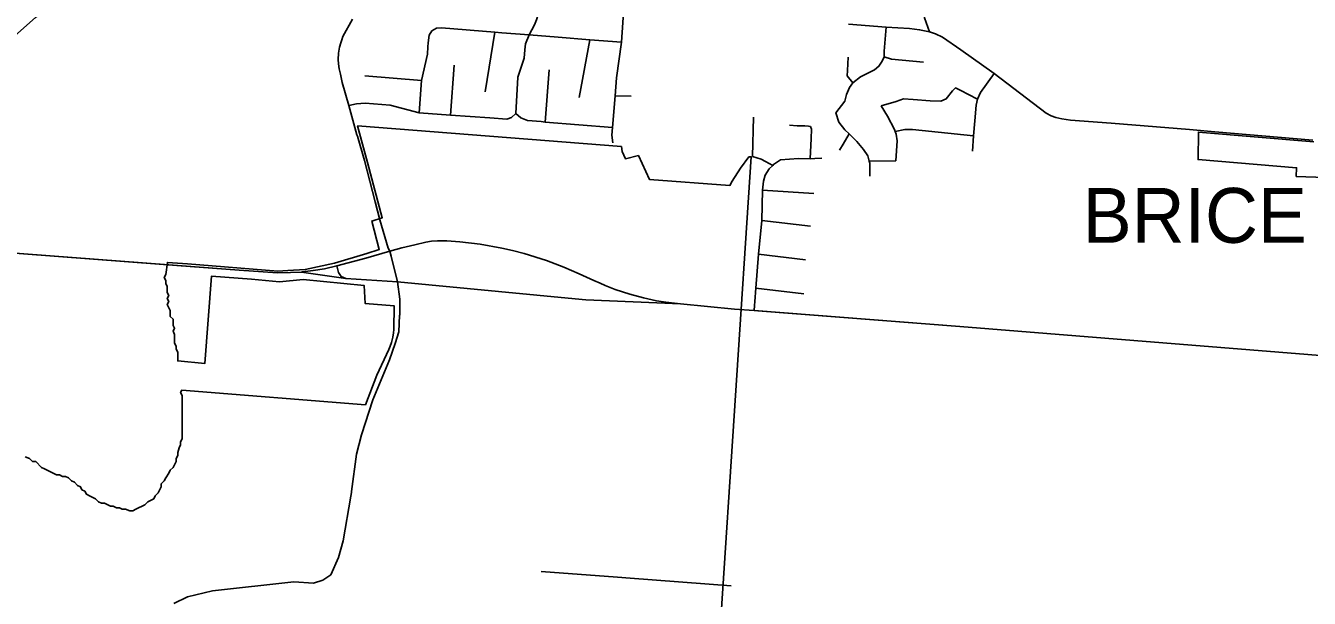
# Model space of a CAD drawing. Extents: x 1729596 to 1934326, y 644115 to 911751.
# Drawn here: x 1863218 to 1874925, y 694653 to 699875 of the extents above; entities that cross this region are included whole.
import ezdxf

# ---------------------------------------------------------------- set-up
doc = ezdxf.new("R2010")
doc.units = 0
for name, color, linetype in [('GM_X_City_Street', 7, 'Continuous'), ('GM_X_Corporation', 7, 'Continuous'), ('GM_X_Corporation_Text', 7, 'Continuous'), ('GM_X_County_Road', 7, 'Continuous'), ('GM_X_Interstate_Route', 7, 'Continuous'), ('GM_X_Township', 7, 'Continuous'), ('GM_X_Township_Road', 7, 'Continuous')]:
    doc.layers.add(name, color=color, linetype=linetype)

msp = doc.modelspace()

# ---------------------------------------------------------------- linework, layer by layer
at = {"layer": 'GM_X_City_Street'}
for points in [[(1867689, 699074), (1867705, 699405), (1867764, 699580), (1867769, 699656), (1867777, 699710), (1867811, 699792), (1867859, 699882), (1867878, 699928), (1867890, 699967), (1867902, 700098), (1867921, 700440), (1867930, 700572), (1867936, 700755), (1867950, 700831), (1867977, 700904), (1867994, 700938), (1868035, 701005)], [(1871460, 699819), (1871415, 699946), (1871415, 700030), (1871420, 700173), (1871424, 700234)], [(1868572, 698806), (1868565, 698876), (1868570, 698945), (1868593, 699236), (1868606, 699398), (1868653, 699725), (1868674, 700037)], [(1866244, 698866), (1866239, 698881), (1866165, 699146), (1866104, 699357), (1866088, 699432), (1866078, 699480), (1866071, 699526), (1866067, 699566), (1866070, 699624), (1866080, 699680), (1866091, 699717), (1866100, 699747), (1866111, 699776), (1866198, 699935)], [(1866922, 699827), (1866964, 699853), (1867010, 699856), (1867496, 699815), (1867561, 699811), (1867811, 699792), (1868074, 699771), (1868363, 699747), (1868653, 699725)], [(1870917, 698502), (1870917, 698622), (1870912, 698639), (1870897, 698688), (1870860, 698747), (1870799, 698819), (1870727, 698889), (1870690, 698925), (1870633, 698996), (1870607, 699079), (1870690, 699188), (1870705, 699246), (1870731, 699310), (1870762, 699355), (1870830, 699409), (1870960, 699473), (1871000, 699505), (1871028, 699550), (1871046, 699590), (1871048, 699643), (1871065, 699862)], [(1870722, 699888), (1871065, 699862), (1871277, 699848), (1871371, 699838), (1871460, 699819), (1871514, 699800), (1871580, 699770), (1871747, 699655), (1872052, 699438), (1872525, 699078), (1872570, 699053), (1872613, 699038), (1872668, 699024), (1872748, 699013), (1873117, 698986), (1873833, 698927), (1874063, 698907)], [(1866807, 699079), (1866829, 699375), (1866881, 699616), (1866885, 699683), (1866888, 699719), (1866899, 699787), (1866922, 699827)], [(1867407, 699273), (1867496, 699815)], [(1868267, 699221), (1868363, 699747)], [(1867092, 699059), (1867127, 699515)], [(1870762, 699355), (1870711, 699419), (1870712, 699467), (1870719, 699588)], [(1871046, 699590), (1871114, 699571), (1871407, 699543)], [(1866312, 699417), (1866829, 699375)], [(1867957, 698996), (1867992, 699471)], [(1871853, 698732), (1871863, 698871), (1871873, 699006), (1871885, 699149), (1871899, 699206), (1871927, 699266), (1872052, 699438)], [(1871020, 699143), (1871158, 699184), (1871223, 699208), (1871311, 699203), (1871468, 699190), (1871564, 699185), (1871614, 699209), (1871672, 699281), (1871699, 699307), (1871745, 699283), (1871815, 699246), (1871899, 699206)], [(1866165, 699146), (1866236, 699163), (1866313, 699167), (1866542, 699151), (1866807, 699079), (1867092, 699059), (1867450, 699033), (1867606, 699022), (1867650, 699039), (1867689, 699074)], [(1868593, 699236), (1868740, 699231)], [(1867689, 699074), (1867734, 699033), (1867793, 699010), (1867919, 699000), (1867957, 698996), (1868570, 698945)], [(1869845, 698682), (1869856, 699040)], [(1871153, 698643), (1871165, 698825), (1871156, 698886), (1871148, 698910), (1871141, 698928), (1871078, 699051), (1871020, 699143)], [(1870371, 698662), (1870381, 698847), (1870385, 698931), (1870375, 698954), (1870357, 698960), (1870325, 698961), (1870253, 698962), (1870184, 698967)], [(1871148, 698910), (1871237, 698928), (1871307, 698927), (1871863, 698871)], [(1866550, 697772), (1866538, 697818), (1866524, 697845), (1866448, 698105), (1866404, 698269), (1866307, 698645), (1866244, 698866)], [(1870639, 698739), (1870674, 698795), (1870727, 698889)], [(1874063, 698907), (1874957, 698831)], [(1869845, 698682), (1869926, 698658), (1869965, 698637), (1870031, 698601)], [(1869861, 697276), (1869864, 697323), (1869867, 697360), (1869878, 697481), (1869902, 697791), (1869931, 698097), (1869938, 698375), (1869948, 698457), (1869963, 698511), (1869998, 698568), (1870031, 698601)], [(1870031, 698601), (1870037, 698610), (1870102, 698650), (1870267, 698663), (1870371, 698662), (1870414, 698663), (1870480, 698666)], [(1870912, 698639), (1871153, 698643)], [(1869938, 698375), (1870407, 698346)], [(1869931, 698097), (1870375, 698046)], [(1862259, 697869), (1862555, 697842), (1864476, 697696)], [(1869902, 697791), (1870329, 697740)], [(1869878, 697481), (1870316, 697430)], [(1869895, 697274), (1871736, 697131), (1875175, 696856)]]:
    msp.add_lwpolyline(points, dxfattribs=at)
at = {"layer": 'GM_X_Corporation'}
for points in [[(1869550, 694325), (1869833, 698679), (1869814, 698680), (1869737, 698577), (1869660, 698456), (1869641, 698418), (1868907, 698473), (1868806, 698690), (1868687, 698662), (1868657, 698726), (1868651, 698772), (1866245, 698962), (1866336, 698628), (1866470, 698123), (1866374, 698093), (1866443, 697834), (1866328, 697798), (1866034, 697709), (1865767, 697650), (1865608, 697641), (1865518, 697637), (1864693, 697702), (1864510, 697716), (1864495, 697606), (1864481, 697579), (1864495, 697551), (1864495, 697524), (1864508, 697497), (1864508, 697469), (1864508, 697442), (1864522, 697415), (1864508, 697388), (1864522, 697360), (1864508, 697333), (1864536, 697279), (1864536, 697224), (1864563, 697197), (1864563, 697142), (1864576, 697115), (1864563, 697088), (1864576, 697060), (1864576, 696979), (1864590, 696951), (1864590, 696924), (1864604, 696897), (1864604, 696818), (1864851, 696794), (1864914, 697591), (1865278, 697562), (1865532, 697538), (1865750, 697559), (1866305, 697505), (1866315, 697341), (1866579, 697320), (1866574, 697105), (1866572, 697073), (1866566, 697034), (1866555, 696987), (1866543, 696952), (1866530, 696922), (1866419, 696689), (1866317, 696418), (1864641, 696550), (1864631, 696529), (1864645, 696501), (1864645, 696229), (1864645, 696106), (1864631, 696079), (1864631, 696052), (1864617, 696024), (1864604, 695983), (1864604, 695956), (1864590, 695929), (1864590, 695902), (1864563, 695847), (1864536, 695820), (1864522, 695793), (1864495, 695752), (1864481, 695724), (1864454, 695697), (1864454, 695670), (1864426, 695615), (1864399, 695588), (1864386, 695561), (1864331, 695533), (1864304, 695506), (1864222, 695465), (1864195, 695452), (1864167, 695452), (1864127, 695465), (1864099, 695465), (1864072, 695479), (1864045, 695479), (1864017, 695493), (1863990, 695493), (1863936, 695520), (1863908, 695520), (1863881, 695533), (1863854, 695561), (1863799, 695588), (1863772, 695602), (1863758, 695629), (1863731, 695643), (1863718, 695670), (1863690, 695683), (1863663, 695711), (1863636, 695724), (1863608, 695752), (1863581, 695765), (1863554, 695765), (1863527, 695779), (1863499, 695779), (1863390, 695833), (1863363, 695847), (1863309, 695902), (1863281, 695902), (1863254, 695929), (1863213, 695942)], [(1874965, 698815), (1873913, 698904), (1873911, 698654), (1874808, 698580), (1874806, 698501), (1875072, 698489)]]:
    msp.add_lwpolyline(points, dxfattribs=at)
at = {"layer": 'GM_X_County_Road'}
for points in [[(1866538, 697818), (1866649, 697848), (1866766, 697876), (1866866, 697900), (1866920, 697909), (1866973, 697914), (1867058, 697913), (1867177, 697905), (1867362, 697883), (1867559, 697847), (1867659, 697824), (1867763, 697798), (1867969, 697733), (1868127, 697672), (1868265, 697613), (1868398, 697552), (1868456, 697526), (1868503, 697506), (1868595, 697469), (1868727, 697427), (1868853, 697394), (1868971, 697366), (1869057, 697354), (1869162, 697341)], [(1865743, 697629), (1865841, 697641), (1865943, 697657), (1866056, 697684), (1866321, 697756), (1866538, 697818)], [(1866610, 697540), (1866550, 697772)], [(1864476, 697696), (1865166, 697644), (1865514, 697621), (1865633, 697623), (1865732, 697627), (1865743, 697629)], [(1866628, 697235), (1866629, 697236), (1866630, 697380), (1866610, 697540)], [(1869162, 697341), (1869190, 697337), (1869683, 697291), (1869861, 697276), (1869895, 697274)], [(1866188, 695618), (1866190, 695628), (1866235, 695967), (1866282, 696143), (1866385, 696462), (1866535, 696827), (1866587, 696977), (1866621, 697084), (1866628, 697235)], [(1864570, 694605), (1864693, 694666), (1864923, 694722), (1865662, 694803), (1865844, 694792), (1865929, 694818), (1866002, 694868), (1866070, 695025), (1866092, 695101), (1866114, 695176), (1866182, 695583), (1866188, 695618)]]:
    msp.add_lwpolyline(points, dxfattribs=at)
at = {"layer": 'GM_X_Interstate_Route'}
msp.add_lwpolyline([(1866661, 702405), (1866135, 702037), (1865754, 701771), (1863948, 700473), (1863307, 699951), (1863118, 699783), (1862753, 699455), (1862463, 699181), (1861921, 698685), (1861760, 698527)], dxfattribs=at)
at = {"layer": 'GM_X_Township'}
msp.add_lwpolyline([(1880623, 696448), (1880621, 696420), (1880175, 696442), (1877589, 696661), (1876119, 696782), (1875611, 696821), (1875175, 696856), (1871736, 697131), (1869861, 697276), (1869683, 697291), (1869190, 697337), (1868327, 697375), (1868165, 697391), (1866610, 697540), (1866139, 697568), (1865732, 697627), (1865633, 697623), (1865514, 697621), (1865166, 697644), (1862555, 697842)], dxfattribs=at)
at = {"layer": 'GM_X_Township_Road'}
for points in [[(1866056, 697684), (1866071, 697623), (1866094, 697589), (1866139, 697568), (1866610, 697540)], [(1867918, 694897), (1868614, 694845), (1868731, 694836), (1868731, 694836)], [(1868731, 694836), (1869653, 694767)]]:
    msp.add_lwpolyline(points, dxfattribs=at)

# ---------------------------------------------------------------- texts
at = {"layer": 'GM_X_Corporation_Text'}
msp.add_text('BRICE', height=500, rotation=0, dxfattribs=at).set_placement((1872859, 697895))

doc.saveas('drawing.dxf')
